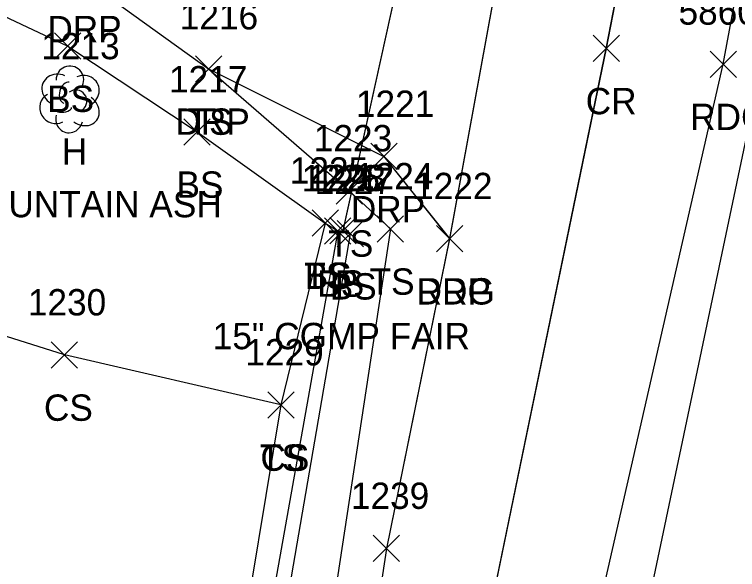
# Model space of a CAD drawing. Extents: x 1554668 to 1563881, y 831386 to 834374.
# Drawn here: x 1561833.7 to 1561888.6, y 833734.2 to 833776.4 of the extents above; entities that cross this region are included whole.
import ezdxf

# ---------------------------------------------------------------- set-up
doc = ezdxf.new("R2010")
doc.units = 0
for name, color, linetype in [('D_A', 7, 'Continuous'), ('D_C', 7, 'Continuous'), ('D_I', 7, 'Continuous'), ('D_TIC', 7, 'Continuous'), ('DCP', 7, 'Continuous'), ('L_A', 7, 'Continuous'), ('L_C', 7, 'Continuous'), ('L_I', 7, 'Continuous'), ('L_TIC', 7, 'Continuous'), ('LELB', 7, 'Continuous'), ('LTD', 7, 'Continuous'), ('P_A', 7, 'Continuous'), ('P_I', 7, 'Continuous'), ('P_TIC', 7, 'Continuous'), ('PET', 7, 'Continuous'), ('PEU', 7, 'Continuous'), ('PRC', 7, 'Continuous'), ('R_A', 7, 'Continuous'), ('R_I', 7, 'Continuous'), ('R_TIC', 7, 'Continuous'), ('RDP', 7, 'Continuous')]:
    doc.layers.add(name, color=color, linetype=linetype)

msp = doc.modelspace()

# ---------------------------------------------------------------- linework, layer by layer
at = {"layer": 'D_TIC'}
for points in [[(1561857.605, 833758.944), (1561859.605, 833760.944)], [(1561859.605, 833758.944), (1561857.605, 833760.944)]]:
    msp.add_lwpolyline(points, dxfattribs=at)
at = {"layer": 'DCP'}
for points in [[(1561864.702, 833787.614), (1561858.605, 833759.939)], [(1561864.702, 833787.614), (1561858.605, 833759.939)], [(1561864.702, 833787.614), (1561858.605, 833759.939)], [(1561864.701, 833787.612), (1561858.605, 833759.944)]]:
    msp.add_lwpolyline(points, dxfattribs=at)
at = {"layer": 'L_TIC'}
for points in [[(1561836.712, 833772.958), (1561838.712, 833774.958)], [(1561838.712, 833772.958), (1561836.712, 833774.958)], [(1561847.403, 833771.22), (1561849.403, 833773.22)], [(1561849.403, 833771.22), (1561847.403, 833773.22)], [(1561846.53, 833766.441), (1561848.53, 833768.441)], [(1561848.53, 833766.441), (1561846.53, 833768.441)], [(1561858.088, 833761.967), (1561860.088, 833763.967)], [(1561860.088, 833761.967), (1561858.088, 833763.967)], [(1561856.265, 833759.518), (1561858.265, 833761.518)], [(1561858.265, 833759.518), (1561856.265, 833761.518)], [(1561856.265, 833759.518), (1561858.265, 833761.518)], [(1561858.265, 833759.518), (1561856.265, 833761.518)], [(1561861.218, 833759.08), (1561863.218, 833761.08)], [(1561863.218, 833759.08), (1561861.218, 833761.08)], [(1561857.213, 833758.926), (1561859.213, 833760.926)], [(1561859.213, 833758.926), (1561857.213, 833760.926)], [(1561857.213, 833758.926), (1561859.213, 833760.926)], [(1561859.213, 833758.926), (1561857.213, 833760.926)], [(1561858.161, 833758.715), (1561860.161, 833760.715)], [(1561860.161, 833758.715), (1561858.161, 833760.715)], [(1561836.467, 833749.508), (1561838.467, 833751.508)], [(1561838.467, 833749.508), (1561836.467, 833751.508)], [(1561852.903, 833745.712), (1561854.903, 833747.712)], [(1561854.903, 833745.712), (1561852.903, 833747.712)], [(1561852.903, 833745.712), (1561854.903, 833747.712)], [(1561854.903, 833745.712), (1561852.903, 833747.712)]]:
    msp.add_lwpolyline(points, dxfattribs=at)
at = {"layer": 'LELB'}
for points in [[(1561812.716, 833374.079), (1561818.656, 833401.248), (1561824.645, 833433.945), (1561832.252, 833470.48), (1561836.457, 833492.444), (1561840.257, 833509.466), (1561848.879, 833557.929), (1561859.972, 833614.877), (1561869.557, 833667.191), (1561878.418, 833715.509), (1561890.593, 833773.388), (1561895.718, 833803.087)], [(1561812.716, 833374.079), (1561818.656, 833401.248), (1561824.645, 833433.945), (1561832.252, 833470.48), (1561836.457, 833492.444), (1561840.257, 833509.466), (1561848.879, 833557.929), (1561859.972, 833614.877), (1561869.557, 833667.191), (1561878.418, 833715.509), (1561890.593, 833773.388), (1561895.718, 833803.087)], [(1561812.716, 833374.079), (1561818.656, 833401.248), (1561824.645, 833433.945), (1561832.252, 833470.48), (1561836.457, 833492.444), (1561840.257, 833509.466), (1561848.879, 833557.929), (1561859.972, 833614.877), (1561869.557, 833667.191), (1561878.418, 833715.509), (1561890.593, 833773.388), (1561895.718, 833803.087)], [(1561812.717, 833374.086), (1561818.657, 833401.257), (1561824.644, 833433.948), (1561832.251, 833470.485), (1561836.455, 833492.446), (1561840.257, 833509.472), (1561848.879, 833557.936), (1561859.973, 833614.873), (1561869.554, 833667.19), (1561878.419, 833715.511), (1561890.594, 833773.393), (1561895.717, 833803.083)], [(1561806.296, 833788.777), (1561837.712, 833773.958), (1561847.53, 833767.441), (1561857.265, 833760.518), (1561858.213, 833759.926), (1561859.161, 833759.715), (1561853.344, 833725.866), (1561846.906, 833696.447), (1561838.604, 833678.002)], [(1561806.297, 833788.773), (1561837.712, 833773.96), (1561847.53, 833767.436), (1561857.266, 833760.521), (1561858.213, 833759.923), (1561859.161, 833759.712), (1561853.344, 833725.864), (1561846.906, 833696.45), (1561838.605, 833677.998)], [(1561806.297, 833788.773), (1561837.712, 833773.96), (1561847.53, 833767.436), (1561857.266, 833760.521), (1561858.213, 833759.923), (1561859.161, 833759.712), (1561853.344, 833725.864), (1561846.906, 833696.45), (1561838.605, 833677.998)], [(1561806.297, 833788.773), (1561837.712, 833773.96), (1561847.53, 833767.436), (1561857.266, 833760.521), (1561858.213, 833759.923), (1561859.161, 833759.712), (1561853.344, 833725.864), (1561846.906, 833696.45), (1561838.605, 833677.998)], [(1561848.403, 833772.22), (1561859.088, 833762.967), (1561862.218, 833760.08), (1561856.867, 833725.001), (1561850.329, 833695.923), (1561848.444, 833676.048), (1561846.147, 833662.128), (1561840.876, 833636.676), (1561837.465, 833618.453), (1561834.406, 833616.246), (1561820.201, 833618.031), (1561806.977, 833621.804), (1561796.8, 833625.141), (1561796.213, 833627.925), (1561779.239, 833633.983)], [(1561848.403, 833772.219), (1561859.088, 833762.966), (1561862.218, 833760.077), (1561856.867, 833725.003), (1561850.329, 833695.921), (1561848.444, 833676.044), (1561846.147, 833662.13), (1561840.875, 833636.672), (1561837.466, 833618.455), (1561834.407, 833616.245), (1561820.203, 833618.032), (1561806.976, 833621.803), (1561796.804, 833625.143), (1561796.218, 833627.927), (1561779.24, 833633.983)], [(1561848.403, 833772.219), (1561859.088, 833762.966), (1561862.218, 833760.077), (1561856.867, 833725.003), (1561850.329, 833695.921), (1561848.444, 833676.044), (1561846.147, 833662.13), (1561840.875, 833636.672), (1561837.466, 833618.455), (1561834.407, 833616.245), (1561820.203, 833618.032), (1561806.976, 833621.803), (1561796.804, 833625.143), (1561796.218, 833627.927), (1561779.24, 833633.983)], [(1561848.403, 833772.219), (1561859.088, 833762.966), (1561862.218, 833760.077), (1561856.867, 833725.003), (1561850.329, 833695.921), (1561848.444, 833676.044), (1561846.147, 833662.13), (1561840.875, 833636.672), (1561837.466, 833618.455), (1561834.407, 833616.245), (1561820.203, 833618.032), (1561806.976, 833621.803), (1561796.804, 833625.143), (1561796.218, 833627.927), (1561779.24, 833633.983)], [(1561857.266, 833760.521), (1561853.903, 833746.709), (1561850.468, 833726.074), (1561842.33, 833696.752), (1561835.928, 833680.605)], [(1561857.266, 833760.521), (1561853.903, 833746.709), (1561850.468, 833726.074), (1561842.33, 833696.752), (1561835.928, 833680.605)], [(1561857.266, 833760.521), (1561853.903, 833746.709), (1561850.468, 833726.074), (1561842.33, 833696.752), (1561835.928, 833680.605)], [(1561857.265, 833760.518), (1561853.903, 833746.712), (1561850.467, 833726.074), (1561842.33, 833696.748), (1561835.929, 833680.601)], [(1561858.213, 833759.923), (1561852.2, 833726.109), (1561845.275, 833696.408), (1561835.928, 833680.605)], [(1561858.213, 833759.923), (1561852.2, 833726.109), (1561845.275, 833696.408), (1561835.928, 833680.605)], [(1561858.213, 833759.923), (1561852.2, 833726.109), (1561845.275, 833696.408), (1561835.928, 833680.605)], [(1561858.213, 833759.926), (1561852.199, 833726.106), (1561845.274, 833696.41), (1561835.929, 833680.601)], [(1561853.903, 833746.712), (1561837.467, 833750.508), (1561809.815, 833759.255)], [(1561853.903, 833746.709), (1561837.467, 833750.506), (1561809.816, 833759.255)], [(1561853.903, 833746.709), (1561837.467, 833750.506), (1561809.816, 833759.255)], [(1561853.903, 833746.709), (1561837.467, 833750.506), (1561809.816, 833759.255)]]:
    msp.add_lwpolyline(points, dxfattribs=at)
at = {"layer": 'LTD'}
msp.add_line((1561837.835, 833769.96), (1561837.835, 833769.96), dxfattribs=at)
msp.add_line((1561837.835, 833769.96), (1561837.835, 833769.96), dxfattribs=at)
msp.add_arc((1561837.882, 833771.394), 1.047, 335.5272, 180.9563, dxfattribs=at)
for centre, major_axis, ratio, start_param, end_param in [((1561837.043, 833770.626), (1.21, -0.512), 0.895232, 1.570796, 4.712389), ((1561838.876, 833770.543), (-1.141, -0.483), 0.949671, 1.570796, 4.712389), ((1561837.627, 833770.418), (-0.208, -0.792), 0.645439, 3.141593, 6.283185), ((1561836.752, 833769.251), (0.584, -1.042), 0.959034, 3.141593, 6.283185), ((1561838.335, 833769.793), (-0.5, 0.667), 0.989748, 3.141593, 6.283185), ((1561838.835, 833769.126), (-1.09, 0.792), 0.841452, 1.570796, 4.712389), ((1561837.377, 833769.209), (-0.625, -0.083), 0.423636, 0, 3.141593), ((1561837.835, 833768.46), (0.265, 1.061), 0.942809, 1.570796, 4.712389)]:
    msp.add_ellipse(centre, major_axis=major_axis, ratio=ratio, start_param=start_param, end_param=end_param, dxfattribs=at)
at = {"layer": 'P_TIC'}
for points in [[(1561877.604, 833772.781), (1561879.604, 833774.781)], [(1561879.604, 833772.781), (1561877.604, 833774.781)], [(1561886.477, 833771.582), (1561888.477, 833773.582)], [(1561888.477, 833771.582), (1561886.477, 833773.582)], [(1561865.706, 833758.336), (1561867.706, 833760.336)], [(1561867.706, 833758.336), (1561865.706, 833760.336)], [(1561860.912, 833734.821), (1561862.912, 833736.821)], [(1561862.912, 833734.821), (1561860.912, 833736.821)], [(1561860.912, 833734.821), (1561862.912, 833736.821)], [(1561862.912, 833734.821), (1561860.912, 833736.821)]]:
    msp.add_lwpolyline(points, dxfattribs=at)
at = {"layer": 'PET'}
for points in [[(1561861.913, 833735.821), (1561859.455, 833719.661), (1561854.908, 833694.543), (1561848.642, 833661.538), (1561838.871, 833614.304), (1561835.262, 833593.716), (1561828.939, 833559.501), (1561819.685, 833511.801), (1561817.414, 833499.273), (1561810.696, 833474.805), (1561802.99, 833435.764), (1561794.155, 833386.844), (1561787.73, 833353.76)], [(1561861.913, 833735.821), (1561859.455, 833719.661), (1561854.908, 833694.543), (1561848.642, 833661.538), (1561838.871, 833614.304), (1561835.262, 833593.716), (1561828.939, 833559.501), (1561819.685, 833511.801), (1561817.414, 833499.273), (1561810.696, 833474.805), (1561802.99, 833435.764), (1561794.155, 833386.844), (1561787.73, 833353.76)], [(1561861.913, 833735.821), (1561859.455, 833719.661), (1561854.908, 833694.543), (1561848.642, 833661.538), (1561838.871, 833614.304), (1561835.262, 833593.716), (1561828.939, 833559.501), (1561819.685, 833511.801), (1561817.414, 833499.273), (1561810.696, 833474.805), (1561802.99, 833435.764), (1561794.155, 833386.844), (1561787.73, 833353.76)], [(1561861.912, 833735.821), (1561859.453, 833719.656), (1561854.907, 833694.541), (1561848.644, 833661.541), (1561838.87, 833614.302), (1561835.26, 833593.712), (1561828.938, 833559.497), (1561819.684, 833511.802), (1561817.414, 833499.277), (1561810.694, 833474.801), (1561802.993, 833435.77), (1561794.153, 833386.847), (1561787.73, 833353.765)]]:
    msp.add_lwpolyline(points, dxfattribs=at)
at = {"layer": 'PEU'}
for points in [[(1561919.943, 834298.234), (1561943.28, 834270.95), (1561951.487, 834242.498), (1561947.428, 834199.982), (1561938.335, 834160.955), (1561930.989, 834108.205), (1561926.196, 834084.148), (1561918.625, 834048.817), (1561911.303, 834007.014), (1561902.907, 833960.116), (1561894.327, 833910.706), (1561885.392, 833863.263), (1561878.367, 833822.842), (1561871.83, 833787.475), (1561866.706, 833759.336), (1561861.912, 833735.821)], [(1561919.942, 834298.234), (1561943.28, 834270.951), (1561951.486, 834242.497), (1561947.431, 834199.985), (1561938.334, 834160.954), (1561930.992, 834108.207), (1561926.199, 834084.149), (1561918.629, 834048.816), (1561911.301, 834007.016), (1561902.906, 833960.119), (1561894.326, 833910.708), (1561885.391, 833863.267), (1561878.367, 833822.843), (1561871.83, 833787.477), (1561866.708, 833759.341), (1561861.913, 833735.821)], [(1561919.942, 834298.234), (1561943.28, 834270.951), (1561951.486, 834242.497), (1561947.431, 834199.985), (1561938.334, 834160.954), (1561930.992, 834108.207), (1561926.199, 834084.149), (1561918.629, 834048.816), (1561911.301, 834007.016), (1561902.906, 833960.119), (1561894.326, 833910.708), (1561885.391, 833863.267), (1561878.367, 833822.843), (1561871.83, 833787.477), (1561866.708, 833759.341), (1561861.913, 833735.821)], [(1561919.942, 834298.234), (1561943.28, 834270.951), (1561951.486, 834242.497), (1561947.431, 834199.985), (1561938.334, 834160.954), (1561930.992, 834108.207), (1561926.199, 834084.149), (1561918.629, 834048.816), (1561911.301, 834007.016), (1561902.906, 833960.119), (1561894.326, 833910.708), (1561885.391, 833863.267), (1561878.367, 833822.843), (1561871.83, 833787.477), (1561866.708, 833759.341), (1561861.913, 833735.821)], [(1561874.546, 833715.874), (1561887.478, 833772.584), (1561893.313, 833803.99), (1561901.362, 833845.453), (1561909.68, 833892.69), (1561910.734, 833900.622), (1561917.511, 833934.31), (1561919.487, 833947.442), (1561923.612, 833973.077), (1561931.593, 834020.004), (1561935.393, 834050.314), (1561943.165, 834094.381), (1561948.419, 834126.576), (1561953.285, 834146.878), (1561956.677, 834158.88)], [(1561874.546, 833715.874), (1561887.478, 833772.584), (1561893.313, 833803.99), (1561901.362, 833845.453), (1561909.68, 833892.69), (1561910.734, 833900.622), (1561917.511, 833934.31), (1561919.487, 833947.442), (1561923.612, 833973.077), (1561931.593, 834020.004), (1561935.393, 834050.314), (1561943.165, 834094.381), (1561948.419, 834126.576), (1561953.285, 834146.878), (1561956.677, 834158.88)], [(1561874.546, 833715.874), (1561887.478, 833772.584), (1561893.313, 833803.99), (1561901.362, 833845.453), (1561909.68, 833892.69), (1561910.734, 833900.622), (1561917.511, 833934.31), (1561919.487, 833947.442), (1561923.612, 833973.077), (1561931.593, 834020.004), (1561935.393, 834050.314), (1561943.165, 834094.381), (1561948.419, 834126.576), (1561953.285, 834146.878), (1561956.677, 834158.88)], [(1561874.547, 833715.877), (1561887.477, 833772.582), (1561893.312, 833803.991), (1561901.361, 833845.451), (1561909.679, 833892.687), (1561910.732, 833900.62), (1561917.51, 833934.306), (1561919.486, 833947.443), (1561923.61, 833973.073), (1561931.592, 834020.003), (1561935.394, 834050.314), (1561943.167, 834094.381), (1561948.417, 834126.574), (1561953.283, 834146.877), (1561956.677, 834158.88)]]:
    msp.add_lwpolyline(points, dxfattribs=at)
at = {"layer": 'PRC'}
for points in [[(1561800.21, 833371.538), (1561806.437, 833405.192), (1561812.654, 833434.931), (1561820.127, 833472.189), (1561827.528, 833505.749), (1561836.938, 833558.608), (1561848.037, 833617.29), (1561858.182, 833669.762), (1561866.962, 833717.246), (1561878.604, 833773.781), (1561885.024, 833806.831), (1561891.658, 833847.81), (1561899.783, 833893.72), (1561902.023, 833902.922), (1561908.115, 833944.075), (1561914.56, 833974.526), (1561922.248, 834021.375), (1561927.368, 834052.029), (1561935.214, 834095.998), (1561945.529, 834150.774)], [(1561800.212, 833371.537), (1561806.439, 833405.19), (1561812.656, 833434.927), (1561820.128, 833472.18), (1561827.529, 833505.744), (1561836.939, 833558.603), (1561848.037, 833617.288), (1561858.18, 833669.759), (1561866.961, 833717.243), (1561878.605, 833773.781), (1561885.024, 833806.829), (1561891.662, 833847.808), (1561899.784, 833893.716), (1561902.024, 833902.921), (1561908.116, 833944.071), (1561914.561, 833974.522), (1561922.249, 834021.372), (1561927.371, 834052.029), (1561935.212, 834095.998), (1561945.527, 834150.773)], [(1561800.212, 833371.537), (1561806.439, 833405.19), (1561812.656, 833434.927), (1561820.128, 833472.18), (1561827.529, 833505.744), (1561836.939, 833558.603), (1561848.037, 833617.288), (1561858.18, 833669.759), (1561866.961, 833717.243), (1561878.605, 833773.781), (1561885.024, 833806.829), (1561891.662, 833847.808), (1561899.784, 833893.716), (1561902.024, 833902.921), (1561908.116, 833944.071), (1561914.561, 833974.522), (1561922.249, 834021.372), (1561927.371, 834052.029), (1561935.212, 834095.998), (1561945.527, 834150.773)], [(1561800.212, 833371.537), (1561806.439, 833405.19), (1561812.656, 833434.927), (1561820.128, 833472.18), (1561827.529, 833505.744), (1561836.939, 833558.603), (1561848.037, 833617.288), (1561858.18, 833669.759), (1561866.961, 833717.243), (1561878.605, 833773.781), (1561885.024, 833806.829), (1561891.662, 833847.808), (1561899.784, 833893.716), (1561902.024, 833902.921), (1561908.116, 833944.071), (1561914.561, 833974.522), (1561922.249, 834021.372), (1561927.371, 834052.029), (1561935.212, 834095.998), (1561945.527, 834150.773)]]:
    msp.add_lwpolyline(points, dxfattribs=at)
at = {"layer": 'R_TIC'}
for points in [[(1561847.403, 833771.22), (1561849.403, 833773.22)], [(1561849.403, 833771.22), (1561847.403, 833773.22)], [(1561860.719, 833764.58), (1561862.719, 833766.58)], [(1561862.719, 833764.58), (1561860.719, 833766.58)], [(1561865.706, 833758.336), (1561867.706, 833760.336)], [(1561867.706, 833758.336), (1561865.706, 833760.336)]]:
    msp.add_lwpolyline(points, dxfattribs=at)
at = {"layer": 'RDP'}
for points in [[(1561806.086, 833793.04), (1561838.678, 833779.249), (1561848.403, 833772.22), (1561861.719, 833765.58), (1561866.706, 833759.336)], [(1561806.087, 833793.04), (1561838.679, 833779.245), (1561848.403, 833772.219), (1561861.719, 833765.577), (1561866.708, 833759.341)], [(1561806.087, 833793.04), (1561838.679, 833779.245), (1561848.403, 833772.219), (1561861.719, 833765.577), (1561866.708, 833759.341)], [(1561806.087, 833793.04), (1561838.679, 833779.245), (1561848.403, 833772.219), (1561861.719, 833765.577), (1561866.708, 833759.341)]]:
    msp.add_lwpolyline(points, dxfattribs=at)

# ---------------------------------------------------------------- texts
at = {"layer": 'D_A'}
msp.add_text('P', height=2, dxfattribs=at).set_placement((1561857.983, 833754.944))
at = {"layer": 'D_C'}
msp.add_text('15" CGMP FAIR', height=2, dxfattribs=at).set_placement((1561848.723, 833750.944))
at = {"layer": 'D_I'}
msp.add_text('1228', height=2, dxfattribs=at).set_placement((1561855.912, 833762.944))
at = {"layer": 'L_A'}
for s, p in [('BS', (1561836.153, 833768.958)), ('TS', (1561846.812, 833767.22)), ('H', (1561837.268, 833764.96)), ('BS', (1561845.971, 833762.441)), ('TS', (1561857.497, 833757.967)), ('TS', (1561855.675, 833755.518)), ('BS', (1561855.706, 833755.518)), ('TS', (1561860.627, 833755.08)), ('BS', (1561856.654, 833754.926)), ('BS', (1561856.654, 833754.926)), ('BS', (1561857.602, 833754.715)), ('CS', (1561835.908, 833745.508)), ('TS', (1561852.313, 833741.712)), ('CS', (1561852.344, 833741.712))]:
    msp.add_text(s, height=2, dxfattribs=at).set_placement(p)
at = {"layer": 'L_C'}
msp.add_text('2S.MOUNTAIN ASH', height=2, dxfattribs=at).set_placement((1561824.89, 833760.96))
at = {"layer": 'L_I'}
for s, p in [('1216', (1561846.222, 833775.22)), ('1213', (1561835.709, 833772.96)), ('1217', (1561845.404, 833770.441)), ('1223', (1561856.395, 833765.967)), ('1225', (1561854.573, 833763.518)), ('1225', (1561854.573, 833763.518)), ('1226', (1561855.465, 833762.926)), ('1226', (1561855.465, 833762.926)), ('1224', (1561859.525, 833763.08)), ('1227', (1561856.468, 833762.715)), ('1230', (1561834.687, 833753.508)), ('1229', (1561851.202, 833749.712)), ('1229', (1561851.202, 833749.712))]:
    msp.add_text(s, height=2, dxfattribs=at).set_placement(p)
at = {"layer": 'P_A'}
for s, p in [('CR', (1561877.038, 833768.781)), ('RDG', (1561884.966, 833767.582)), ('RDG', (1561864.194, 833754.336))]:
    msp.add_text(s, height=2, dxfattribs=at).set_placement(p)
at = {"layer": 'P_I'}
for s, p in [('5860', (1561884.084, 833775.582)), ('1222', (1561864.013, 833762.336)), ('1239', (1561859.212, 833738.821)), ('1239', (1561859.212, 833738.821))]:
    msp.add_text(s, height=2, dxfattribs=at).set_placement(p)
at = {"layer": 'R_A'}
for p in [(1561836.166, 833774.249), (1561845.891, 833767.22), (1561859.207, 833760.58), (1561864.194, 833754.336)]:
    msp.add_text('DRP', height=2, dxfattribs=at).set_placement(p)
at = {"layer": 'R_I'}
for s, p in [('1216', (1561846.222, 833775.22)), ('1221', (1561859.593, 833768.58)), ('1222', (1561864.013, 833762.336))]:
    msp.add_text(s, height=2, dxfattribs=at).set_placement(p)

doc.saveas('drawing.dxf')
